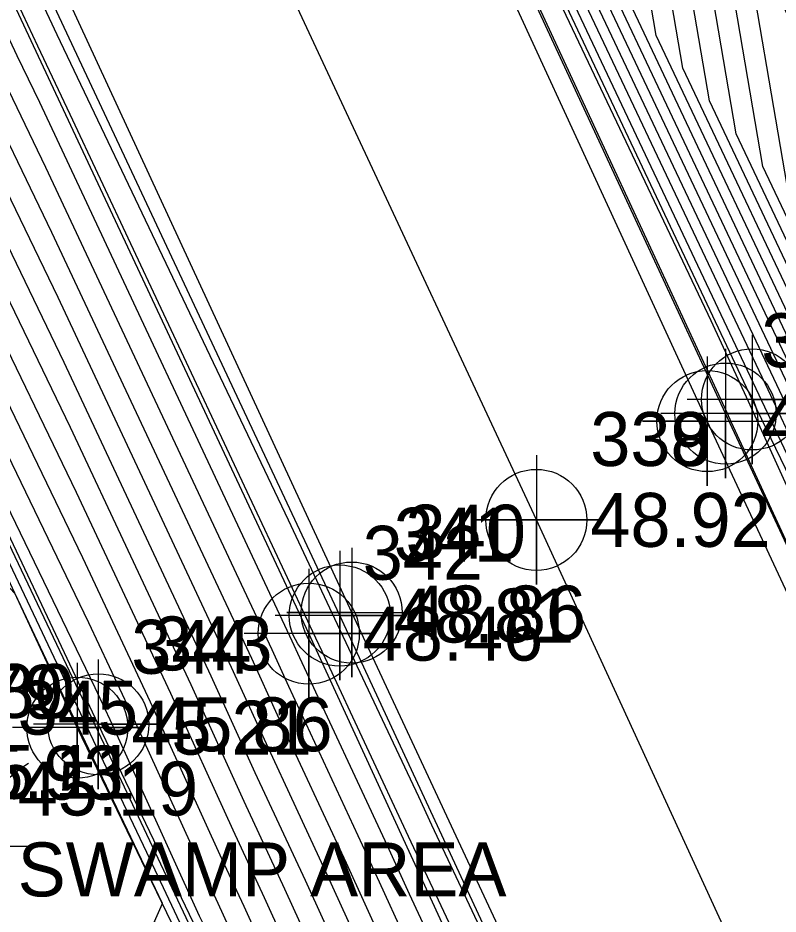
# Model space of a CAD drawing. Extents: x 2090860 to 2091277, y 159470 to 160080.
# Drawn here: x 2090946.32 to 2090981.55, y 159942.65 to 159984.21 of the extents above; entities that cross this region are included whole.
import ezdxf

# ---------------------------------------------------------------- set-up
doc = ezdxf.new("R2010")
doc.units = 0
for name, color, linetype in [('DTM Contours Major', 7, 'Continuous'), ('DTM Contours Minor', 7, 'Continuous'), ('Exist DTM Breakline', 7, 'Continuous'), ('Exist DTM Breakline Cogo Elevation', 7, 'Continuous'), ('Exist DTM Breakline Cogo Number', 7, 'Continuous'), ('Exist DTM Breakline Cogo Point CELL', 7, 'Continuous'), ('Exist DTM Crownline', 7, 'Continuous'), ('Exist DTM Crownline Cogo Elevation', 7, 'Continuous'), ('Exist DTM Crownline Cogo Number', 7, 'Continuous'), ('Exist DTM Crownline Cogo Point CELL', 7, 'Continuous'), ('Exist Hydro Swamp or Marsh', 7, 'Continuous'), ('Exist Hydro Swamp or Marsh Cogo Comment', 7, 'Continuous'), ('Exist Hydro Swamp or Marsh Cogo Elevation', 7, 'Continuous'), ('Exist Hydro Swamp or Marsh Cogo Number', 7, 'Continuous'), ('Exist Roads EOP', 7, 'Continuous'), ('Exist Roads EOP Cogo Elevation', 7, 'Continuous'), ('Exist Roads EOP Cogo Number', 7, 'Continuous'), ('Exist Roads EOP Cogo Point CELL', 7, 'Continuous'), ('Exist Roads EOT', 7, 'Continuous'), ('Exist Roads EOT Cogo Elevation', 7, 'Continuous'), ('Exist Roads EOT Cogo Number', 7, 'Continuous'), ('Exist Roads EOT Cogo Point CELL', 7, 'Continuous')]:
    doc.layers.add(name, color=color, linetype=linetype)

msp = doc.modelspace()

# ---------------------------------------------------------------- linework, layer by layer
at = {"layer": 'DTM Contours Major'}
for points in [[(2091021.025, 159898.877), (2091011.639, 159919.455), (2091005.482, 159932.957), (2091005.012, 159933.952), (2090993.094, 159961.193), (2090992.991, 159961.428), (2090991.418, 159965.023), (2090992.968, 159961.452), (2090985.925, 159965.485), (2090984.33, 159968.87), (2090979.616, 159978.837), (2090976.348, 159997.974), (2090975.965, 159998.781), (2090963.783, 160025.207), (2090963.068, 160026.714), (2090951.202, 160052.433), (2090950.873, 160053.127), (2090947.083, 160061.339), (2090947.113, 160061.357)], [(2091021.18, 159890.907), (2091013.639, 159907.174), (2091008.516, 159918.108), (2091005.725, 159924.066), (2091001.855, 159932.408), (2090996.755, 159943.477), (2090989.564, 159959.773), (2090985.428, 159962.142), (2090982.708, 159967.911), (2090974.675, 159984.898), (2090972.744, 159996.202), (2090967.23, 160007.833), (2090960.061, 160023.383), (2090954.323, 160035.484), (2090947.368, 160050.56), (2090945.472, 160054.558), (2090943.253, 160059.365), (2090943.413, 160059.46)], [(2091015.949, 159893.794), (2091005.233, 159916.667), (2090999.394, 159929.129), (2090998.605, 159930.829), (2090988.204, 159953.404), (2090986.126, 159958.114), (2090984.93, 159958.799), (2090981.087, 159966.952), (2090969.734, 159990.958), (2090969.141, 159994.43), (2090958.495, 160016.884), (2090956.34, 160021.56), (2090945.578, 160044.255), (2090943.533, 160048.687), (2090940.07, 160055.988), (2090939.423, 160057.391), (2090939.712, 160057.563)], [(2090915.092, 160045.426), (2090922.919, 160028.827), (2090925.677, 160023.356), (2090935.836, 160001.778), (2090938.587, 159996.284), (2090939.794, 159993.785), (2090945.294, 159982.053), (2090947.597, 159977.284), (2090958.084, 159954.914), (2090958.856, 159953.218), (2090962.481, 159945.429), (2090964.802, 159940.332), (2090975.096, 159918.212), (2090976.136, 159916.102), (2090980.927, 159905.726), (2090983.402, 159900.704)], [(2090910.606, 160043.392), (2090913.448, 160037.366), (2090921.532, 160021.331), (2090926.001, 160011.839), (2090934.731, 159994.403), (2090938.563, 159986.471), (2090941.418, 159980.382), (2090948.738, 159965.223), (2090954.329, 159953.296), (2090956.792, 159947.89), (2090958.683, 159943.825), (2090966.198, 159927.322), (2090971.199, 159916.575), (2090974.729, 159909.419), (2090977.08, 159904.325)], [(2090907.426, 160041.969), (2090911.786, 160032.768), (2090917.984, 160019.602), (2090928.464, 159997.339), (2090930.876, 159992.521), (2090937.332, 159979.157), (2090937.542, 159978.71), (2090949.879, 159953.162), (2090950.574, 159951.679), (2090954.727, 159942.562), (2090954.886, 159942.222), (2090962.638, 159925.196), (2090966.571, 159916.855), (2090967.464, 159914.985), (2090973.015, 159903.605)]]:
    msp.add_lwpolyline(points, dxfattribs=at)
at = {"layer": 'DTM Contours Minor'}
for points in [[(2091023.606, 159891.972), (2091011.906, 159917.209), (2091010.978, 159919.19), (2091010.473, 159920.269), (2091004.292, 159933.592), (2091003.168, 159936.032), (2090992.143, 159961.018), (2090985.801, 159964.649), (2090983.924, 159968.63), (2090978.381, 159980.353), (2090975.447, 159997.531), (2090973.781, 160001.044), (2090962.852, 160024.751), (2090960.882, 160028.906), (2090950.243, 160051.965), (2090949.523, 160053.484), (2090946.126, 160060.846), (2090946.188, 160060.883)], [(2091022.798, 159891.617), (2091012.484, 159913.864), (2091010.158, 159918.829), (2091008.89, 159921.535), (2091003.48, 159933.198), (2091001.03, 159938.513), (2090991.283, 159960.603), (2090985.677, 159963.813), (2090983.519, 159968.391), (2090977.145, 159981.868), (2090974.546, 159997.088), (2090971.598, 160003.307), (2090961.922, 160024.295), (2090958.696, 160031.099), (2090949.285, 160051.497), (2090948.173, 160053.842), (2090945.168, 160060.352), (2090945.263, 160060.408)], [(2091021.989, 159891.262), (2091013.061, 159910.519), (2091009.337, 159918.469), (2091007.307, 159922.8), (2091002.667, 159932.803), (2090998.893, 159940.995), (2090990.424, 159960.188), (2090985.552, 159962.978), (2090983.114, 159968.151), (2090975.91, 159983.383), (2090973.645, 159996.645), (2090969.414, 160005.57), (2090960.992, 160023.839), (2090956.509, 160033.292), (2090948.326, 160051.028), (2090946.822, 160054.2), (2090944.211, 160059.859), (2090944.338, 160059.934)], [(2091014.217, 159903.829), (2091007.695, 159917.748), (2091004.142, 159925.332), (2091001.042, 159932.013), (2090994.617, 159945.959), (2090988.704, 159959.359), (2090985.303, 159961.306), (2090982.303, 159967.671), (2090973.44, 159986.413), (2090971.844, 159995.759), (2090965.046, 160010.096), (2090959.131, 160022.927), (2090952.137, 160037.677), (2090946.409, 160050.092), (2090944.121, 160054.915), (2090942.296, 160058.872), (2090942.487, 160058.986)], [(2091014.794, 159900.484), (2091006.874, 159917.387), (2091002.559, 159926.597), (2091000.23, 159931.619), (2090992.479, 159948.441), (2090987.845, 159958.944), (2090985.179, 159960.47), (2090981.898, 159967.432), (2090972.204, 159987.928), (2090970.943, 159995.316), (2090962.863, 160012.359), (2090958.2, 160022.472), (2090949.95, 160039.87), (2090945.45, 160049.623), (2090942.771, 160055.273), (2090941.338, 160058.378), (2090941.562, 160058.512)], [(2091015.372, 159897.139), (2091006.054, 159917.027), (2091000.976, 159927.863), (2090999.417, 159931.224), (2090990.342, 159950.923), (2090986.985, 159958.529), (2090985.054, 159959.635), (2090981.492, 159967.192), (2090970.969, 159989.443), (2090970.042, 159994.873), (2090960.679, 160014.622), (2090957.27, 160022.016), (2090947.764, 160042.063), (2090944.492, 160049.155), (2090941.421, 160055.631), (2090940.381, 160057.885), (2090940.637, 160058.037)], [(2091016.527, 159890.449), (2091004.412, 159916.306), (2090997.811, 159930.395), (2090997.792, 159930.434), (2090986.066, 159955.886), (2090985.266, 159957.699), (2090984.806, 159957.963), (2090980.682, 159966.713), (2090968.499, 159992.473), (2090968.24, 159993.988), (2090956.311, 160019.147), (2090955.409, 160021.104), (2090943.391, 160046.448), (2090942.575, 160048.218), (2090938.72, 160056.346), (2090938.465, 160056.898), (2090938.787, 160057.089)], [(2091009.719, 159902.684), (2091003.488, 159915.918), (2091000.285, 159922.734), (2090996.873, 159929.981), (2090990.78, 159943.197), (2090984.364, 159957.258), (2090983.277, 159959.617), (2090980.176, 159966.423), (2090978.448, 159970.155), (2090967.363, 159993.547), (2090966.269, 159995.909), (2090955.847, 160017.91), (2090953.21, 160023.496), (2090943.221, 160044.585), (2090940.726, 160049.87), (2090937.604, 160056.462), (2090937.861, 160056.615)], [(2091015.092, 159888.281), (2091005.494, 159908.792), (2091002.253, 159915.399), (2090998.196, 159923.671), (2090995.587, 159929.309), (2090993.655, 159934.254), (2090987.577, 159947.689), (2090983.614, 159956.284), (2090983.391, 159956.773), (2090979.397, 159965.44), (2090979.189, 159965.897), (2090967.415, 159991.324), (2090966.567, 159993.113), (2090960.639, 160005.911), (2090959.796, 160007.69), (2090947.752, 160033.198), (2090947.057, 160034.665), (2090937.109, 160055.735), (2090936.921, 160056.131), (2090936.936, 160056.14)], [(2090918.443, 160047.072), (2090925.071, 160032.691), (2090928.75, 160024.871), (2090936.833, 160007.361), (2090941.384, 159997.661), (2090946.344, 159987.242), (2090948.128, 159983.436), (2090958.851, 159960.931), (2090960.998, 159956.352), (2090964.881, 159948.099), (2090965.492, 159946.787), (2090977.739, 159920.762), (2090978.261, 159919.644), (2090983.592, 159908.064), (2090984.057, 159907.047), (2090994.33, 159884.723)], [(2090917.335, 160046.443), (2090927.654, 160024.558), (2090927.75, 160024.369), (2090931.7, 160015.979), (2090940.501, 159997.22), (2090941.185, 159995.783), (2090947.222, 159982.907), (2090948.733, 159979.736), (2090959.976, 159955.756), (2090960.546, 159954.544), (2090964.408, 159946.258), (2090966.553, 159941.699), (2090977.104, 159919.081), (2090978.421, 159916.221), (2090982.884, 159906.464), (2090984.288, 159903.411)], [(2090916.214, 160045.934), (2090925.287, 160026.693), (2090926.714, 160023.863), (2090938.295, 159999.263), (2090939.55, 159996.755), (2090940.102, 159995.614), (2090946.263, 159982.47), (2090947.312, 159980.299), (2090959.023, 159955.318), (2090959.373, 159954.55), (2090963.43, 159945.83), (2090964.452, 159943.584), (2090976.07, 159918.621), (2090976.488, 159917.773), (2090981.889, 159906.077), (2090983.02, 159903.782)], [(2090913.971, 160044.918), (2090920.551, 160030.962), (2090924.641, 160022.85), (2090933.377, 160004.293), (2090937.623, 159995.814), (2090939.486, 159991.957), (2090944.325, 159981.635), (2090947.882, 159974.268), (2090957.145, 159954.509), (2090958.34, 159951.886), (2090961.531, 159945.028), (2090965.151, 159937.08), (2090974.122, 159917.803), (2090975.785, 159914.432), (2090979.965, 159905.376)], [(2090912.849, 160044.409), (2090918.183, 160033.097), (2090923.605, 160022.344), (2090930.919, 160006.809), (2090936.659, 159995.344), (2090939.178, 159990.128), (2090943.356, 159981.217), (2090948.168, 159971.253), (2090956.207, 159954.105), (2090957.824, 159950.554), (2090960.582, 159944.627), (2090965.5, 159933.827), (2090973.148, 159917.393), (2090975.433, 159912.761), (2090979.004, 159905.026)], [(2090911.728, 160043.901), (2090915.815, 160035.231), (2090922.569, 160021.838), (2090928.46, 160009.324), (2090935.695, 159994.873), (2090938.871, 159988.3), (2090942.387, 159980.799), (2090948.453, 159968.238), (2090955.268, 159953.701), (2090957.308, 159949.222), (2090959.632, 159944.226), (2090965.849, 159930.575), (2090972.174, 159916.984), (2090975.081, 159911.09), (2090978.042, 159904.675)], [(2090909.485, 160042.884), (2090911.08, 160039.501), (2090920.496, 160020.825), (2090923.543, 160014.354), (2090933.768, 159993.933), (2090938.255, 159984.643), (2090940.449, 159979.964), (2090949.023, 159962.207), (2090953.39, 159952.892), (2090956.276, 159946.558), (2090957.734, 159943.424), (2090966.547, 159924.07), (2090970.225, 159916.166), (2090974.377, 159907.749), (2090976.119, 159903.975)], [(2090908.363, 160042.375), (2090908.712, 160041.635), (2090919.46, 160020.319), (2090921.084, 160016.87), (2090932.804, 159993.462), (2090937.948, 159982.814), (2090939.48, 159979.546), (2090949.308, 159959.192), (2090952.452, 159952.487), (2090955.76, 159945.226), (2090956.784, 159943.023), (2090966.896, 159920.817), (2090969.251, 159915.756), (2090974.025, 159906.078), (2090975.157, 159903.624)], [(2090907.788, 160042.123), (2090909.613, 160038.271), (2090916.596, 160023.437), (2090918.424, 160019.813), (2090918.625, 160019.385), (2090931.84, 159992.992), (2090937.64, 159980.985), (2090938.511, 159979.128), (2090949.594, 159956.177), (2090951.513, 159952.083), (2090955.244, 159943.894), (2090955.835, 159942.622), (2090967.245, 159917.565), (2090968.277, 159915.347), (2090973.673, 159904.407)], [(2090906.701, 160041.663), (2090916.132, 160021.763), (2090917.301, 160019.278), (2090919.911, 160013.734), (2090930.148, 159992.169), (2090935.256, 159981.379), (2090936.616, 159978.521), (2090944.254, 159962.401), (2090949.505, 159951.363), (2090952.287, 159945.521), (2090954.079, 159941.72), (2090957.972, 159933.464), (2090966.981, 159914.593), (2090968.004, 159912.496), (2090972.898, 159902.775)], [(2090907.064, 160041.816), (2090913.959, 160027.266), (2090917.643, 160019.44), (2090925.862, 160001.979), (2090930.45, 159992.315), (2090932.739, 159987.48), (2090936.984, 159978.555), (2090940.085, 159972.01), (2090949.879, 159951.423), (2090950.719, 159949.661), (2090954.36, 159941.937), (2090962.272, 159925.16), (2090967.223, 159914.789), (2090970.51, 159908.05), (2090973.119, 159902.868)], [(2090977.922, 159994.472), (2090988.528, 159970.658), (2090991.852, 159962.998), (2090986.05, 159966.321), (2090984.735, 159969.11), (2090980.851, 159977.322), (2090977.922, 159994.472)], [(2090979.783, 159989.293), (2090988.123, 159970.567), (2090990.737, 159964.544), (2090986.174, 159967.156), (2090985.14, 159969.35), (2090982.086, 159975.807), (2090979.783, 159989.293)], [(2090971.838, 159903.298), (2090965.559, 159913.825), (2090960.005, 159918.329), (2090953.785, 159940.417), (2090952.656, 159942.311), (2090953.018, 159943.141), (2090949.131, 159951.303), (2090948.423, 159952.793), (2090946.196, 159957.493), (2090935.425, 159968.942), (2090923.729, 159986.244), (2090932.971, 159966.138), (2090934.711, 159962.399), (2090939.74, 159951.48), (2090940.783, 159949.239), (2090943.605, 159943.01), (2090953.294, 159921.983), (2090957.425, 159912.812), (2090965.766, 159894.719)]]:
    msp.add_lwpolyline(points, dxfattribs=at)
at = {"layer": 'Exist DTM Breakline'}
for points in [[(2091054.851, 159814.302), (2091016.781, 159888.977), (2090997.773, 159930.425), (2090980.346, 159966.514), (2090937.845, 160056.578)], [(2091012.481, 159842.709), (2090995.611, 159879.293), (2090976.725, 159918.896), (2090959.8, 159955.653), (2090940.36, 159997.15), (2090917.627, 160046.575)], [(2091019.809, 159801.913), (2091004.418, 159836.946), (2090986.475, 159875.987), (2090967.517, 159915.028), (2090950.041, 159951.449), (2090930.695, 159992.433), (2090908.049, 160042.233)], [(2091019.111, 159801.55), (2091003.076, 159836.513), (2090986.016, 159875.809), (2090966.872, 159914.505), (2090949.073, 159951.294), (2090930.109, 159992.15), (2090906.432, 160041.549)]]:
    msp.add_lwpolyline(points, dxfattribs=at)
at = {"layer": 'Exist DTM Breakline Cogo Point CELL'}
for points in [[(2090980.346, 159969.514), (2090980.346, 159963.514), (2090980.346, 159966.514), (2090983.346, 159966.514), (2090977.346, 159966.514)], [(2090959.8, 159958.653), (2090959.8, 159952.653), (2090959.8, 159955.653), (2090962.8, 159955.653), (2090956.8, 159955.653)], [(2090949.073, 159954.294), (2090949.073, 159948.294), (2090949.073, 159951.294), (2090952.073, 159951.294), (2090946.073, 159951.294)], [(2090950.041, 159954.449), (2090950.041, 159948.449), (2090950.041, 159951.449), (2090953.041, 159951.449), (2090947.041, 159951.449)]]:
    msp.add_lwpolyline(points, dxfattribs=at)
for centre in [(2090980.346, 159966.514), (2090959.8, 159955.653), (2090949.073, 159951.294), (2090950.041, 159951.449)]:
    msp.add_circle(centre, 2.344, dxfattribs=at)
at = {"layer": 'Exist DTM Crownline'}
msp.add_lwpolyline([(2091041.896, 159807.58), (2091022.738, 159848.476), (2091006.16, 159884.052), (2090987.202, 159924.29), (2090970.349, 159960.929), (2090951.234, 160001.943), (2090928.333, 160051.748)], dxfattribs=at)
at = {"layer": 'Exist DTM Crownline Cogo Point CELL'}
msp.add_lwpolyline([(2090970.349, 159963.929), (2090970.349, 159957.929), (2090970.349, 159960.929), (2090973.349, 159960.929), (2090967.349, 159960.929)], dxfattribs=at)
msp.add_circle((2090970.349, 159960.929), 2.344, dxfattribs=at)
at = {"layer": 'Exist Hydro Swamp or Marsh'}
msp.add_lwpolyline([(2090940.581, 159945.797), (2090943.807, 159945.797), (2090943.807, 159951.714), (2090943.807, 159945.797), (2090947.032, 159945.797)], dxfattribs=at)
msp.add_arc((2090950.648, 159943.524), 7.208, 122.1274, 161.6222, dxfattribs=at)
at = {"layer": 'Exist Roads EOP'}
for points in [[(2091050.887, 159811.953), (2091031.567, 159853.358), (2091015.44, 159888.433), (2090996.018, 159929.558), (2090979.118, 159965.859), (2090960.144, 160006.791), (2090936.877, 160056.11)], [(2091032.873, 159803.467), (2091013.956, 159843.468), (2090996.901, 159879.939), (2090978.321, 159919.673), (2090961.239, 159956.493), (2090941.84, 159997.888), (2090918.792, 160047.284)]]:
    msp.add_lwpolyline(points, dxfattribs=at)
at = {"layer": 'Exist Roads EOP Cogo Point CELL'}
for points in [[(2090979.118, 159968.859), (2090979.118, 159962.859), (2090979.118, 159965.859), (2090982.118, 159965.859), (2090976.118, 159965.859)], [(2090961.239, 159959.493), (2090961.239, 159953.493), (2090961.239, 159956.493), (2090964.239, 159956.493), (2090958.239, 159956.493)]]:
    msp.add_lwpolyline(points, dxfattribs=at)
for centre in [(2090979.118, 159965.859), (2090961.239, 159956.493)]:
    msp.add_circle(centre, 2.344, dxfattribs=at)
at = {"layer": 'Exist Roads EOT'}
for points in [[(2091050.358, 159811.619), (2091030.997, 159852.885), (2091014.318, 159887.944), (2090995.228, 159929.102), (2090978.274, 159965.509), (2090959.414, 160006.451), (2090936.296, 160055.791)], [(2091033.429, 159803.706), (2091014.624, 159843.758), (2090997.608, 159880.208), (2090978.895, 159919.952), (2090961.789, 159956.632), (2090942.516, 159998.302), (2090919.608, 160047.643)]]:
    msp.add_lwpolyline(points, dxfattribs=at)
at = {"layer": 'Exist Roads EOT Cogo Point CELL'}
for points in [[(2090978.274, 159968.509), (2090978.274, 159962.509), (2090978.274, 159965.509), (2090975.274, 159965.509), (2090981.274, 159965.509)], [(2090970.349, 159963.929), (2090970.349, 159957.929), (2090970.349, 159960.929), (2090967.349, 159960.929), (2090973.349, 159960.929)], [(2090961.789, 159959.632), (2090961.789, 159953.632), (2090961.789, 159956.632), (2090958.789, 159956.632), (2090964.789, 159956.632)]]:
    msp.add_lwpolyline(points, dxfattribs=at)
for centre in [(2090978.274, 159965.509), (2090970.349, 159960.929), (2090961.789, 159956.632)]:
    msp.add_circle(centre, 2.344, dxfattribs=at)

# ---------------------------------------------------------------- texts
at = {"layer": 'Exist DTM Breakline Cogo Elevation'}
for s, p in [('48.46', (2090962.3, 159954.403)), ('45.86', (2090952.541, 159950.199)), ('45.21', (2090951.573, 159950.044)), ('45.93', (2090942.853, 159947.957)), ('45.11', (2090943.371, 159947.996))]:
    msp.add_text(s, height=2.5, dxfattribs=at).set_placement(p)
at = {"layer": 'Exist DTM Breakline Cogo Number'}
for s, p in [('342', (2090962.3, 159958.153)), ('344', (2090951.573, 159953.794)), ('343', (2090952.541, 159953.949)), ('480', (2090943.371, 159951.746)), ('479', (2090942.853, 159951.707))]:
    msp.add_text(s, height=2.5, dxfattribs=at).set_placement(p)
at = {"layer": 'Exist DTM Crownline Cogo Elevation'}
msp.add_text('48.92', height=2.5, dxfattribs=at).set_placement((2090972.849, 159959.679))
at = {"layer": 'Exist DTM Crownline Cogo Number'}
msp.add_text('338', height=2.5, dxfattribs=at).set_placement((2090972.849, 159963.429))
at = {"layer": 'Exist Hydro Swamp or Marsh Cogo Comment'}
msp.add_text('SWAMP AREA', height=2.5, dxfattribs=at).set_placement((2090946.306, 159943.471))
at = {"layer": 'Exist Hydro Swamp or Marsh Cogo Elevation'}
msp.add_text('45.19', height=2.5, dxfattribs=at).set_placement((2090946.306, 159947.221))
at = {"layer": 'Exist Hydro Swamp or Marsh Cogo Number'}
msp.add_text('345', height=2.5, dxfattribs=at).set_placement((2090946.306, 159950.971))
at = {"layer": 'Exist Roads EOP Cogo Elevation'}
msp.add_text('48.81', height=2.5, dxfattribs=at).set_placement((2090963.739, 159955.243))
at = {"layer": 'Exist Roads EOP Cogo Number'}
msp.add_text('341', height=2.5, dxfattribs=at).set_placement((2090963.739, 159958.993))
at = {"layer": 'Exist Roads EOT Cogo Elevation'}
for s, p in [('48.86', (2090980.774, 159964.259)), ('48.92', (2090972.849, 159959.679)), ('48.86', (2090964.289, 159955.382))]:
    msp.add_text(s, height=2.5, dxfattribs=at).set_placement(p)
at = {"layer": 'Exist Roads EOT Cogo Number'}
for s, p in [('337', (2090980.774, 159968.009)), ('339', (2090972.849, 159963.429)), ('340', (2090964.289, 159959.132))]:
    msp.add_text(s, height=2.5, dxfattribs=at).set_placement(p)

doc.saveas('drawing.dxf')
